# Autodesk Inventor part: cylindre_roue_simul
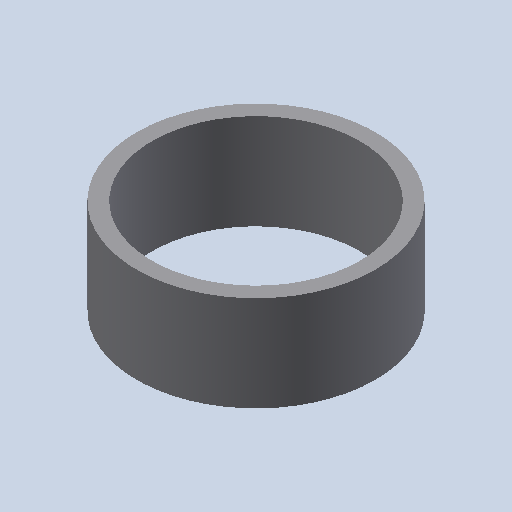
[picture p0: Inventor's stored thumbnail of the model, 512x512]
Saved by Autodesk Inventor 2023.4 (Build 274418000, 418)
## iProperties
Created: 2011-01
Part Number: cylindre_roue_simul
Document SubType Name: Modeling
Designer: eric
Density: 1 g/cm^3
Mass: 1188.48 g
Surface Area: 1706.83 cm^2
Volume: 1188.48 cm^3
Material: Générique
Appearance: Par défaut
Author: eric
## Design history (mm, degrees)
sketch "Esquisse1"
  geometry: C1 r 108.821 at (-117.821, 0) reference; C2 r 125 at (-117.821, 0)
  constraints: 1 centre point, 1 coincident
  dimensions: "d0" = 250 diameter of C2
extrude "Extrusion1" new body sketch "Esquisse1" distance "d1" = 100; taper "d2" = 0 deg
node "Solide1"
node "Corps solides"
node "Corps surfaciques"
node "Référence1"
